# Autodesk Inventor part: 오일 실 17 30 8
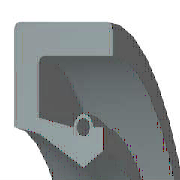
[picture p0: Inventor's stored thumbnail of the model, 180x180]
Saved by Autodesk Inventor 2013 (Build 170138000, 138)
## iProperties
IsCustomPart: 1
Created: 2012-02
Part Number: 오일 실 17 30 8
Material: 고무
Description: 오일-실
Document SubType Name: Modeling
Standard: KS B 2804
Designer: mduedu
Standards Organization: KS
Language: ko-KR
Size Designation: S - 17 30 8
Categories: <MemberInstance><Categories><Category DisplayName="샤프트 부품" InternalName="7f7aeb1f-a693-4053-b835-cee3144e0d98" Mnemonic="SHFT"><Category DisplayName="실링" Intern
Density: 0.93 g/cm^3
Author: mduedu
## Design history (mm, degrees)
revolve "본체" stored, may be unused: angle "d17" = 90 deg
revolve "스프링1" stored, may be unused: angle "d18" = 90 deg
body "Solid1"
sketch "스케치1"
  geometry: L1 (0, 15)-(8, 15); L2 (8, 15)-(8, 13.75); L3 (8, 13.75)-(1.75, 13.75); L4 (0, 15)-(0, 10.6); L5 (0, 10.6)-(1.75, 10.25); L6 (1.75, 10.25)-(4.9, 8.5); L7 (4.9, 8.5)-(0, 8.5); L8 (6.3, 9.375)-(6.3, 10.6); L9 (0, 0)-(9.586, 0) reference; L10 (4.9, 8.5)-(6.3, 9.375); L11 (0, 18)-(0, -3) reference; L12 (-1.917, 0)-(11.503, 0) reference; L13 (4.2, 10.6)-(1.75, 11.09); L14 (1.75, 11.09)-(1.75, 13.75); L15 (6.3, 10.6)-(5.6, 10.6); C1 r 0.455 at (4.9, 10.6); A1 r 0.7 centre (4.9, 10.6) between (5.6, 10.6) and (4.2, 10.6)
  constraints: 26 end point, 5 horizontal alignment, 4 perpendicular, 2 centre point, 2 collinear, 2 horizontal, 2 parallel, 2 point on circle, 2 point on line, 2 vertical alignment, 1 coincident
  dimensions: "d0" = 30 diameter of L1 L9 (= SD2); "d1" = 18.75 diameter of L8.start L9 (= ABDM); "d2" = 1.25 distance of L1.end L2.end (computed from SD); "d3" = 0.91 diameter of C1 (= SPDI); "d4" = 1.4 diameter of A1 (= SPDA); "d5" = 17 diameter of L6.end L9 (= NND); "d6" = 20.5 diameter of L5.end L9 (= TKDM); "d7" = 21.2 diameter of L4.end L9 (= HLDM); "d8" = 4.9 distance from line of C1.centre L4 (= SPDST); "d9" = 6.3 distance between parallel lines of L8 L4 (= SDI); "d10" = 8 distance between parallel lines of L2 L4 (= SWDT); "d12" = 1.75 distance between parallel lines of L14 L4 (= SD)
fillet "모깎기1" dims "d11" = 0.5 (= RR)
other parameters: "SD2" = 30 [user parameter; used in 1 equation term], "SWDT" = 8 [user parameter; used in 1 equation term], "RR" = 0.5 [user parameter; used in 1 equation term], "SD" = 1.75 [user parameter; used in 2 equation terms], "NND" = 17 [user parameter; used in 1 equation term], "SPDA" = 1.4 [user parameter; used in 1 equation term], "SPDI" = 0.91 [user parameter; used in 1 equation term], "TKDM" = 20.5 [user parameter; used in 1 equation term], "HLDM" = 21.2 [user parameter; used in 1 equation term], "ABDM" = 18.75 [user parameter; used in 1 equation term], "SDI" = 6.3 [user parameter; used in 1 equation term], "SPDST" = 4.9 [user parameter; used in 1 equation term], "d13" = 0, "d14" = 0, "d15" = 0, "LAB" = 0.35 [user parameter]
